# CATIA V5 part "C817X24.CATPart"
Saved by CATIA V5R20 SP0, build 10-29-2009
Part number: C817X24
Source: Unknown
Property "A": "80.0"
Property "ARTICLENO": "C817XC24"
Property "B": "18"
Property "BOMINFO": "C817XC24"
Property "C": "19.0"
Property "CA": "C817XC24"
Property "D": "52"
Property "DES": "EYEBOLT TWISTER WITH BEARING M24 WITH KEY"
Property "E": "73"
Property "F": "44.5"
Property "K": "88"
Property "L": "38.5"
Property "LINA": "C817XC24"
Property "NB": "C817XC24"
Property "NBSYN": "$CODE."
Property "NN": "C817X"
Property "NT": "Eyebolt twister with bearing"
Property "SIZE": "M24"
Property "SUPPLIER": "CF"
Property "WEIGHT": "2050"
Property "WLL": "3.20"
Bounding box of the stored display mesh (mm): x -44 to 44, y -38.5 to 98, z -38.944 to 38.944
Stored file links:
  C:\Users\Utente\Desktop\3D files 817X\C817X24.CATPart
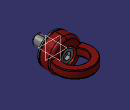
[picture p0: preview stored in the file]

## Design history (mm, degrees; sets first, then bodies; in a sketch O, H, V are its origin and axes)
Body1 "Geometry.1" (main body)
  Solid1 "C817XC24.catpart": solid without history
